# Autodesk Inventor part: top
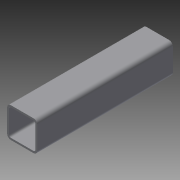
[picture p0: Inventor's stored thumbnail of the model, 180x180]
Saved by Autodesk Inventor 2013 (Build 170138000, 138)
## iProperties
Created: 2008-04
Part Number: top
Document SubType Name: Modeling
Designer: Jayson Martinez
Density: 1 g/cm^3
Material: Generic
Author: Jayson Martinez
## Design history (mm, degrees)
sketch "Sketch1"
  geometry: L1 (6.35, 0)-(44.45, 0); L2 (50.8, 6.35)-(50.8, 44.45); L3 (44.45, 50.8)-(6.35, 50.8); L4 (0, 44.45)-(0, 6.35); L5 (3.175, 6.35)-(3.175, 44.45); L6 (6.35, 47.625)-(44.45, 47.625); L7 (47.625, 44.45)-(47.625, 6.35); L8 (44.45, 3.175)-(6.35, 3.175); A1 r 6.35 centre (6.35, 44.45) between (6.35, 50.8) and (0, 44.45); A2 r 6.35 centre (44.45, 44.45) between (50.8, 44.45) and (44.45, 50.8); A3 r 6.35 centre (44.45, 6.35) between (44.45, 0) and (50.8, 6.35); A4 r 6.35 centre (6.35, 6.35) between (0, 6.35) and (6.35, 0); A5 r 3.175 centre (6.35, 44.45) between (6.35, 47.625) and (3.175, 44.45); A6 r 3.175 centre (44.45, 44.45) between (47.625, 44.45) and (44.45, 47.625); A7 r 3.175 centre (44.45, 6.35) between (44.45, 3.175) and (47.625, 6.35); A8 r 3.175 centre (6.35, 6.35) between (3.175, 6.35) and (6.35, 3.175); 3 further points
  constraints: 16 end point, 16 point on circle, 8 centre point, 8 tangent, 6 point on line, 4 parallel, 3 equal radius, 2 perpendicular, 1 horizontal, 7 other
  dimensions: "d0" = 50.8 distance of point (0, 0) point (50.8, 0) (= MemberWidth); "d1" = 50.8 distance of point (0, 50.8) point (0, 0) (= d0); "d2" = 6.35 radius of A1 (= 2 x MemberThickness); "d3" = 3.175 distance between parallel lines of L2 L7 (= MemberThickness)
extrude "Extrusion1" new body sketch "Sketch1" distance "d4" = 228.6 (= -0.5 x MemberWidth + 0.5 x HorizontalLength); taper "d5" = 0 deg
workplane "Work Plane1"
body "Solid1"
other parameters: "d7" = -25.4 (= -0.5 x MemberWidth), "MemberThickness" = 3.175, "MemberWidth" = 50.8, "HorizontalLength" = 508
